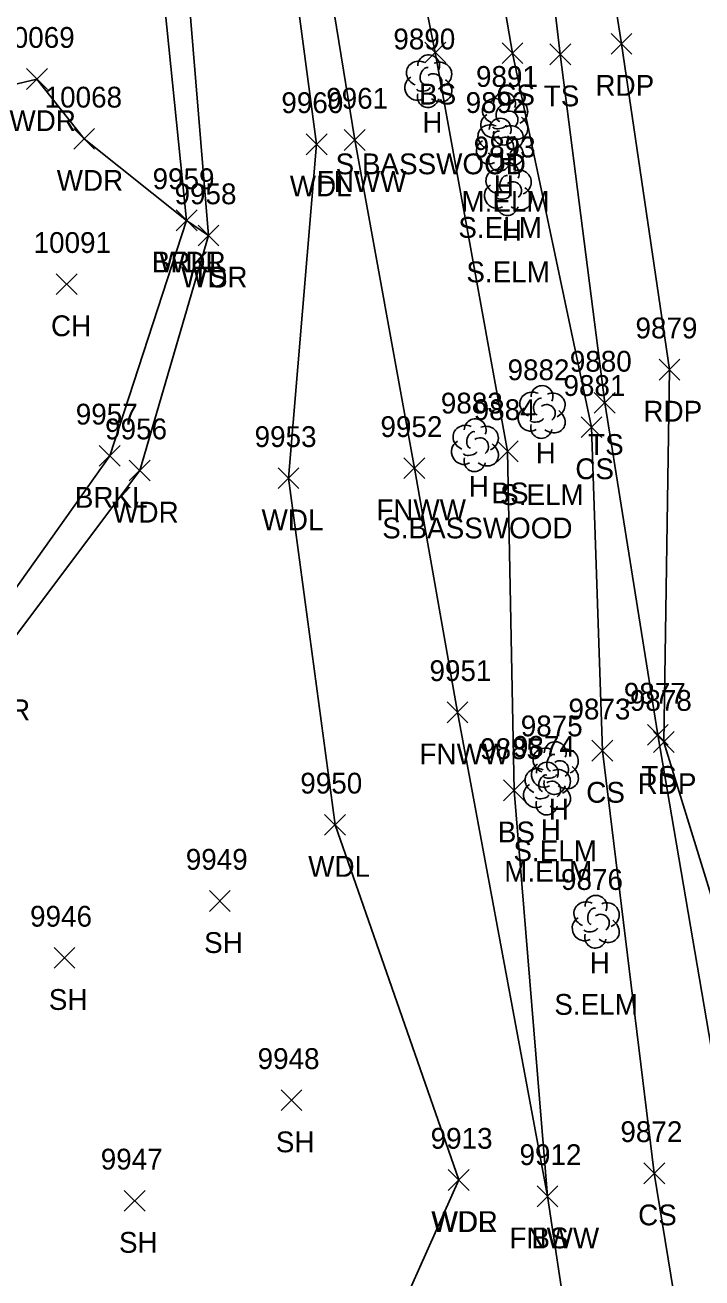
# Model space of a CAD drawing. Extents: x 1439173 to 1457902, y 641926 to 659889.
# Drawn here: x 1448141.5 to 1448206.5, y 646731.6 to 646852 of the extents above; entities that cross this region are included whole.
import ezdxf

# ---------------------------------------------------------------- set-up
doc = ezdxf.new("R2010")
doc.units = 0
for name, color, linetype in [('L_A', 7, 'Continuous'), ('L_C', 7, 'Continuous'), ('L_I', 7, 'Continuous'), ('L_TIC', 7, 'Continuous'), ('LAWA', 7, 'Continuous'), ('LAWE', 7, 'Continuous'), ('LELB', 7, 'Continuous'), ('LFNC', 7, 'Continuous'), ('LTD', 7, 'Continuous'), ('P_A', 7, 'Continuous'), ('P_I', 7, 'Continuous'), ('P_TIC', 7, 'Continuous'), ('PET', 7, 'Continuous')]:
    doc.layers.add(name, color=color, linetype=linetype)

msp = doc.modelspace()

# ---------------------------------------------------------------- linework, layer by layer
at = {"layer": 'L_TIC'}
for points in [[(1448179.87, 646848.4), (1448181.87, 646850.4)], [(1448181.87, 646848.4), (1448179.87, 646850.4)], [(1448187.29, 646848.33), (1448189.29, 646850.33)], [(1448189.29, 646848.33), (1448187.29, 646850.33)], [(1448187.29, 646848.33), (1448189.29, 646850.33)], [(1448189.29, 646848.33), (1448187.29, 646850.33)], [(1448191.88, 646848.23), (1448193.88, 646850.23)], [(1448193.88, 646848.23), (1448191.88, 646850.23)], [(1448141.6, 646845.85), (1448143.6, 646847.85)], [(1448143.6, 646845.85), (1448141.6, 646847.85)], [(1448146.14, 646840.11), (1448148.14, 646842.11)], [(1448148.14, 646840.11), (1448146.14, 646842.11)], [(1448168.47, 646839.58), (1448170.47, 646841.58)], [(1448170.47, 646839.58), (1448168.47, 646841.58)], [(1448172.13, 646840), (1448174.13, 646842)], [(1448174.13, 646840), (1448172.13, 646842)], [(1448155.98, 646832.27), (1448157.98, 646834.27)], [(1448157.98, 646832.27), (1448155.98, 646834.27)], [(1448155.98, 646832.27), (1448157.98, 646834.27)], [(1448157.98, 646832.27), (1448155.98, 646834.27)], [(1448158.08, 646830.82), (1448160.08, 646832.82)], [(1448160.08, 646830.82), (1448158.08, 646832.82)], [(1448158.08, 646830.82), (1448160.08, 646832.82)], [(1448160.08, 646830.82), (1448158.08, 646832.82)], [(1448144.46, 646826.14), (1448146.46, 646828.14)], [(1448146.46, 646826.14), (1448144.46, 646828.14)], [(1448196.14, 646814.73), (1448198.14, 646816.73)], [(1448198.14, 646814.73), (1448196.14, 646816.73)], [(1448194.88, 646812.4), (1448196.88, 646814.4)], [(1448196.88, 646812.4), (1448194.88, 646814.4)], [(1448148.59, 646809.65), (1448150.59, 646811.65)], [(1448150.59, 646809.65), (1448148.59, 646811.65)], [(1448186.82, 646810.08), (1448188.82, 646812.08)], [(1448188.82, 646810.08), (1448186.82, 646812.08)], [(1448186.82, 646810.08), (1448188.82, 646812.08)], [(1448188.82, 646810.08), (1448186.82, 646812.08)], [(1448151.47, 646808.23), (1448153.47, 646810.23)], [(1448153.47, 646808.23), (1448151.47, 646810.23)], [(1448177.86, 646808.45), (1448179.86, 646810.45)], [(1448179.86, 646808.45), (1448177.86, 646810.45)], [(1448165.77, 646807.49), (1448167.77, 646809.49)], [(1448167.77, 646807.49), (1448165.77, 646809.49)], [(1448182.01, 646785), (1448184.01, 646787)], [(1448184.01, 646785), (1448182.01, 646787)], [(1448201.24, 646782.83), (1448203.24, 646784.83)], [(1448203.24, 646782.83), (1448201.24, 646784.83)], [(1448195.92, 646781.31), (1448197.92, 646783.31)], [(1448197.92, 646781.31), (1448195.92, 646783.31)], [(1448187.43, 646777.5), (1448189.43, 646779.5)], [(1448189.43, 646777.5), (1448187.43, 646779.5)], [(1448170.24, 646774.19), (1448172.24, 646776.19)], [(1448172.24, 646774.19), (1448170.24, 646776.19)], [(1448159.17, 646766.87), (1448161.17, 646768.87)], [(1448161.17, 646766.87), (1448159.17, 646768.87)], [(1448144.25, 646761.4), (1448146.25, 646763.4)], [(1448146.25, 646761.4), (1448144.25, 646763.4)], [(1448166.06, 646747.72), (1448168.06, 646749.72)], [(1448168.06, 646747.72), (1448166.06, 646749.72)], [(1448200.91, 646740.7), (1448202.91, 646742.7)], [(1448202.91, 646740.7), (1448200.91, 646742.7)], [(1448182.12, 646740.06), (1448184.12, 646742.06)], [(1448184.12, 646740.06), (1448182.12, 646742.06)], [(1448182.12, 646740.06), (1448184.12, 646742.06)], [(1448184.12, 646740.06), (1448182.12, 646742.06)], [(1448150.99, 646738.06), (1448152.99, 646740.06)], [(1448152.99, 646738.06), (1448150.99, 646740.06)], [(1448190.65, 646738.49), (1448192.65, 646740.49)], [(1448192.65, 646738.49), (1448190.65, 646740.49)], [(1448190.65, 646738.49), (1448192.65, 646740.49)], [(1448192.65, 646738.49), (1448190.65, 646740.49)]]:
    msp.add_lwpolyline(points, dxfattribs=at)
at = {"layer": 'LAWA'}
for points in [[(1448183.12, 646741.06), (1448171.24, 646775.19), (1448166.77, 646808.49), (1448169.47, 646840.58), (1448166.51, 646862.79), (1448166.95, 646881.82), (1448167.02, 646894.53), (1448164.97, 646897.76), (1448155.95, 646904.34), (1448145.42, 646911.6), (1448139.79, 646908.56)], [(1448122.26, 646730.64), (1448122.34, 646733.36), (1448124.58, 646744.9), (1448118.56, 646753.05), (1448120.3, 646764.71), (1448138.2, 646790.24), (1448152.47, 646809.23), (1448159.08, 646831.82), (1448156.98, 646833.27), (1448147.14, 646841.11), (1448142.6, 646846.85), (1448137.7, 646845.7), (1448133.51, 646846.6), (1448126.04, 646850.08), (1448117.8, 646850.56), (1448101.43, 646849.6), (1448092.75, 646843.14), (1448093.37, 646850.31), (1448088.78, 646863.36)], [(1448183.12, 646741.06), (1448174.83, 646722.49)]]:
    msp.add_lwpolyline(points, dxfattribs=at)
at = {"layer": 'LAWE'}
msp.add_lwpolyline([(1448119.67, 646730.17), (1448121.01, 646743.71), (1448116.17, 646751.8), (1448115.93, 646763.95), (1448135.32, 646790.55), (1448149.59, 646810.65), (1448156.98, 646833.27), (1448154.13, 646861.31)], dxfattribs=at)
at = {"layer": 'LELB'}
for points in [[(1448221.02, 646679.97), (1448216.65, 646707.27), (1448209.17, 646743.3), (1448202.24, 646783.83), (1448197.14, 646815.73), (1448192.88, 646849.23), (1448188.79, 646883.91), (1448185.57, 646916.7), (1448180.61, 646928.95), (1448176.05, 646935.8), (1448168.91, 646942.17), (1448163.03, 646939.76)], [(1448188.29, 646849.33), (1448182.45, 646883.23), (1448180.07, 646902.07), (1448180.06, 646909.38)], [(1448159.08, 646831.82), (1448156.64, 646861.39), (1448153.18, 646884.54), (1448157.08, 646891.59), (1448167.02, 646894.53), (1448174.4, 646898.52), (1448175.16, 646902.85)], [(1448187.82, 646811.08), (1448180.87, 646849.4), (1448174.09, 646883.06), (1448180.07, 646902.07)], [(1448185.32, 646643.7), (1448191.92, 646652.09), (1448196.88, 646659.22), (1448211.78, 646670.71), (1448213.3, 646681.39), (1448207.76, 646705.84), (1448201.91, 646741.7), (1448196.92, 646782.31), (1448195.88, 646813.4), (1448188.29, 646849.33)], [(1448187.82, 646811.08), (1448188.43, 646778.5), (1448191.65, 646739.49)]]:
    msp.add_lwpolyline(points, dxfattribs=at)
at = {"layer": 'LFNC'}
msp.add_lwpolyline([(1448099.82, 646655.95), (1448102.02, 646656.12), (1448112.07, 646658.89), (1448125.11, 646661.46), (1448146.72, 646665.17), (1448181.19, 646670.55), (1448193.45, 646673.01), (1448200.73, 646682.46), (1448197.31, 646702.04), (1448191.65, 646739.49), (1448183.01, 646786), (1448178.86, 646809.45), (1448173.13, 646841), (1448169.61, 646862.71), (1448166.95, 646881.82), (1448157.08, 646891.59), (1448153.58, 646895.82), (1448145.42, 646911.6)], dxfattribs=at)
at = {"layer": 'LTD'}
for p, q in [((1448180.18, 646846.7), (1448180.18, 646846.7)), ((1448180.18, 646846.7), (1448180.18, 646846.7)), ((1448187.48, 646843.1), (1448187.48, 646843.1)), ((1448187.48, 646843.1), (1448187.48, 646843.1)), ((1448187.05, 646840.59), (1448187.05, 646840.59)), ((1448187.05, 646840.59), (1448187.05, 646840.59)), ((1448187.82, 646836.32), (1448187.82, 646836.32)), ((1448187.82, 646836.32), (1448187.82, 646836.32)), ((1448191.07, 646814.91), (1448191.07, 646814.91)), ((1448191.07, 646814.91), (1448191.07, 646814.91)), ((1448184.66, 646811.71), (1448184.66, 646811.71)), ((1448184.66, 646811.71), (1448184.66, 646811.71)), ((1448192.34, 646780.69), (1448192.34, 646780.69)), ((1448192.34, 646780.69), (1448192.34, 646780.69)), ((1448191.58, 646778.72), (1448191.58, 646778.72)), ((1448191.58, 646778.72), (1448191.58, 646778.72)), ((1448196.26, 646765.93), (1448196.26, 646765.93)), ((1448196.26, 646765.93), (1448196.26, 646765.93))]:
    msp.add_line(p, q, dxfattribs=at)
for centre in [(1448180.23, 646848.13), (1448187.52, 646844.54), (1448187.1, 646842.03), (1448187.87, 646837.76), (1448191.12, 646816.34), (1448184.7, 646813.15), (1448192.39, 646782.12), (1448191.63, 646780.16), (1448196.31, 646767.36)]:
    msp.add_arc(centre, 1.05, 335.5272, 180.9563, dxfattribs=at)
for centre, major_axis, ratio, start_param, end_param in [((1448179.39, 646847.37), (1.21, -0.51), 0.895232, 1.570796, 4.712389), ((1448181.22, 646847.28), (-1.14, -0.48), 0.949671, 1.570796, 4.712389), ((1448179.97, 646847.16), (-0.208, -0.792), 0.645439, 3.141593, 6.283185), ((1448180.68, 646846.53), (-0.5, 0.667), 0.989748, 3.141593, 6.283185), ((1448179.1, 646845.99), (0.58, -1.04), 0.959034, 3.141593, 6.283185), ((1448179.72, 646845.95), (-0.625, -0.083), 0.423636, 0, 3.141593), ((1448181.18, 646845.87), (-1.09, 0.79), 0.841452, 1.570796, 4.712389), ((1448180.18, 646845.2), (0.26, 1.06), 0.942809, 1.570796, 4.712389), ((1448186.68, 646843.77), (1.21, -0.51), 0.895232, 1.570796, 4.712389), ((1448188.52, 646843.69), (-1.14, -0.48), 0.949671, 1.570796, 4.712389), ((1448187.27, 646843.56), (-0.208, -0.792), 0.645439, 3.141593, 6.283185), ((1448187.98, 646842.94), (-0.5, 0.667), 0.989748, 3.141593, 6.283185), ((1448186.26, 646841.26), (1.21, -0.51), 0.895232, 1.570796, 4.712389), ((1448186.39, 646842.39), (0.58, -1.04), 0.959034, 3.141593, 6.283185), ((1448187.02, 646842.35), (-0.625, -0.083), 0.423636, 0, 3.141593), ((1448188.09, 646841.18), (-1.14, -0.48), 0.949671, 1.570796, 4.712389), ((1448188.48, 646842.27), (-1.09, 0.79), 0.841452, 1.570796, 4.712389), ((1448186.84, 646841.05), (-0.208, -0.792), 0.645439, 3.141593, 6.283185), ((1448187.48, 646841.6), (0.26, 1.06), 0.942809, 1.570796, 4.712389), ((1448187.55, 646840.43), (-0.5, 0.667), 0.989748, 3.141593, 6.283185), ((1448185.97, 646839.88), (0.58, -1.04), 0.959034, 3.141593, 6.283185), ((1448186.59, 646839.84), (-0.625, -0.083), 0.423636, 0, 3.141593), ((1448188.05, 646839.76), (-1.09, 0.79), 0.841452, 1.570796, 4.712389), ((1448187.05, 646839.09), (0.26, 1.06), 0.942809, 1.570796, 4.712389), ((1448187.03, 646836.99), (1.21, -0.51), 0.895232, 1.570796, 4.712389), ((1448187.61, 646836.78), (-0.208, -0.792), 0.645439, 3.141593, 6.283185), ((1448188.86, 646836.91), (-1.14, -0.48), 0.949671, 1.570796, 4.712389), ((1448186.74, 646835.61), (0.58, -1.04), 0.959034, 3.141593, 6.283185), ((1448188.32, 646836.16), (-0.5, 0.667), 0.989748, 3.141593, 6.283185), ((1448188.82, 646835.49), (-1.09, 0.79), 0.841452, 1.570796, 4.712389), ((1448187.82, 646834.82), (0.26, 1.06), 0.942809, 1.570796, 4.712389), ((1448187.36, 646835.57), (-0.625, -0.083), 0.423636, 0, 3.141593), ((1448190.28, 646815.57), (1.21, -0.51), 0.895232, 1.570796, 4.712389), ((1448190.86, 646815.37), (-0.208, -0.792), 0.645439, 3.141593, 6.283185), ((1448192.11, 646815.49), (-1.14, -0.48), 0.949671, 1.570796, 4.712389), ((1448189.99, 646814.2), (0.58, -1.04), 0.959034, 3.141593, 6.283185), ((1448191.57, 646814.74), (-0.5, 0.667), 0.989748, 3.141593, 6.283185), ((1448192.07, 646814.07), (-1.09, 0.79), 0.841452, 1.570796, 4.712389), ((1448183.87, 646812.38), (1.21, -0.51), 0.895232, 1.570796, 4.712389), ((1448185.7, 646812.3), (-1.14, -0.48), 0.949671, 1.570796, 4.712389), ((1448191.07, 646813.41), (0.26, 1.06), 0.942809, 1.570796, 4.712389), ((1448190.61, 646814.16), (-0.625, -0.083), 0.423636, 0, 3.141593), ((1448184.45, 646812.17), (-0.208, -0.792), 0.645439, 3.141593, 6.283185), ((1448185.16, 646811.55), (-0.5, 0.667), 0.989748, 3.141593, 6.283185), ((1448183.57, 646811), (0.58, -1.04), 0.959034, 3.141593, 6.283185), ((1448184.2, 646810.96), (-0.625, -0.083), 0.423636, 0, 3.141593), ((1448185.66, 646810.88), (-1.09, 0.79), 0.841452, 1.570796, 4.712389), ((1448184.66, 646810.21), (0.26, 1.06), 0.942809, 1.570796, 4.712389), ((1448191.55, 646781.36), (1.21, -0.51), 0.895232, 1.570796, 4.712389), ((1448193.38, 646781.27), (-1.14, -0.48), 0.949671, 1.570796, 4.712389), ((1448191.26, 646779.98), (0.58, -1.04), 0.959034, 3.141593, 6.283185), ((1448192.13, 646781.15), (-0.208, -0.792), 0.645439, 3.141593, 6.283185), ((1448192.84, 646780.52), (-0.5, 0.667), 0.989748, 3.141593, 6.283185), ((1448190.79, 646779.39), (1.21, -0.51), 0.895232, 1.570796, 4.712389), ((1448191.37, 646779.18), (-0.208, -0.792), 0.645439, 3.141593, 6.283185), ((1448191.89, 646779.94), (-0.625, -0.083), 0.423636, 0, 3.141593), ((1448192.62, 646779.31), (-1.14, -0.48), 0.949671, 1.570796, 4.712389), ((1448193.34, 646779.86), (-1.09, 0.79), 0.841452, 1.570796, 4.712389), ((1448190.5, 646778.01), (0.58, -1.04), 0.959034, 3.141593, 6.283185), ((1448192.34, 646779.19), (0.26, 1.06), 0.942809, 1.570796, 4.712389), ((1448192.08, 646778.55), (-0.5, 0.667), 0.989748, 3.141593, 6.283185), ((1448192.58, 646777.89), (-1.09, 0.79), 0.841452, 1.570796, 4.712389), ((1448191.58, 646777.22), (0.26, 1.06), 0.942809, 1.570796, 4.712389), ((1448191.12, 646777.97), (-0.625, -0.083), 0.423636, 0, 3.141593), ((1448195.47, 646766.59), (1.21, -0.51), 0.895232, 1.570796, 4.712389), ((1448197.31, 646766.51), (-1.14, -0.48), 0.949671, 1.570796, 4.712389), ((1448196.06, 646766.39), (-0.208, -0.792), 0.645439, 3.141593, 6.283185), ((1448196.76, 646765.76), (-0.5, 0.667), 0.989748, 3.141593, 6.283185), ((1448195.18, 646765.22), (0.58, -1.04), 0.959034, 3.141593, 6.283185), ((1448195.81, 646765.18), (-0.625, -0.083), 0.423636, 0, 3.141593), ((1448197.26, 646765.1), (-1.09, 0.79), 0.841452, 1.570796, 4.712389), ((1448196.26, 646764.43), (0.26, 1.06), 0.942809, 1.570796, 4.712389)]:
    msp.add_ellipse(centre, major_axis=major_axis, ratio=ratio, start_param=start_param, end_param=end_param, dxfattribs=at)
at = {"layer": 'P_TIC'}
for points in [[(1448197.76, 646849.24), (1448199.76, 646851.24)], [(1448199.76, 646849.24), (1448197.76, 646851.24)], [(1448202.37, 646817.93), (1448204.37, 646819.93)], [(1448204.37, 646817.93), (1448202.37, 646819.93)], [(1448201.82, 646782.14), (1448203.82, 646784.14)], [(1448203.82, 646782.14), (1448201.82, 646784.14)]]:
    msp.add_lwpolyline(points, dxfattribs=at)
at = {"layer": 'PET'}
msp.add_lwpolyline([(1448246.46, 646550.34), (1448240.19, 646586.21), (1448237.44, 646603.85), (1448232.82, 646631.59), (1448226.85, 646667.5), (1448220.22, 646707.78), (1448215.23, 646742.97), (1448202.82, 646783.14), (1448203.37, 646818.93), (1448198.76, 646850.24), (1448193.44, 646884.14), (1448187.94, 646917.18), (1448185.3, 646933.85), (1448181.56, 646957.89), (1448177.35, 646983.4)], dxfattribs=at)

# ---------------------------------------------------------------- texts
at = {"layer": 'L_A'}
for s, p in [('BS', (1448179.31, 646844.4)), ('CS', (1448186.73, 646844.33)), ('CS', (1448186.73, 646844.33)), ('TS', (1448191.29, 646844.23)), ('WDR', (1448139.96, 646841.85)), ('H', (1448179.62, 646841.7)), ('H', (1448186.91, 646838.1)), ('WDR', (1448144.5, 646836.11)), ('WDL', (1448166.89, 646835.58)), ('FNWW', (1448169.48, 646836)), ('H', (1448186.49, 646835.59)), ('H', (1448187.25, 646831.32)), ('BRKL', (1448153.63, 646828.27)), ('WDR', (1448154.34, 646828.27)), ('WDR', (1448156.44, 646826.82)), ('TS', (1448157.49, 646826.82)), ('CH', (1448143.95, 646822.14)), ('TS', (1448195.55, 646810.73)), ('H', (1448190.51, 646809.91)), ('CS', (1448194.32, 646808.4)), ('H', (1448184.09, 646806.71)), ('BRKL', (1448146.24, 646805.65)), ('BS', (1448186.26, 646806.08)), ('BS', (1448186.26, 646806.08)), ('WDR', (1448149.83, 646804.23)), ('FNWW', (1448175.2, 646804.45)), ('WDL', (1448164.18, 646803.49)), ('WDR', (1448135.56, 646785.24)), ('FNWW', (1448179.35, 646781)), ('TS', (1448200.65, 646778.83)), ('CS', (1448195.37, 646777.31)), ('H', (1448191.78, 646775.69)), ('BS', (1448186.87, 646773.5)), ('H', (1448191.01, 646773.72)), ('WDL', (1448168.66, 646770.19)), ('SH', (1448158.66, 646762.87)), ('H', (1448195.7, 646760.93)), ('SH', (1448143.74, 646757.4)), ('SH', (1448165.55, 646743.72)), ('CS', (1448200.35, 646736.7)), ('WDR', (1448180.48, 646736.06)), ('WDL', (1448180.53, 646736.06)), ('FNWW', (1448188, 646734.49)), ('BS', (1448190.1, 646734.49)), ('SH', (1448150.48, 646734.06))]:
    msp.add_text(s, height=2, dxfattribs=at).set_placement(p)
at = {"layer": 'L_C'}
for s, p in [('S.BASSWOOD', (1448171.29, 646837.7)), ('M.ELM', (1448183.38, 646834.1)), ('S.ELM', (1448183.08, 646831.59)), ('S.ELM', (1448183.85, 646827.32)), ('S.ELM', (1448187.1, 646805.91)), ('S.BASSWOOD', (1448175.77, 646802.71)), ('S.ELM', (1448188.37, 646771.69)), ('M.ELM', (1448187.49, 646769.72)), ('S.ELM', (1448192.3, 646756.93))]:
    msp.add_text(s, height=2, dxfattribs=at).set_placement(p)
at = {"layer": 'L_I'}
for s, p in [('10069', (1448138.79, 646849.85)), ('9890', (1448176.84, 646849.7)), ('9891', (1448184.78, 646846.1)), ('10068', (1448143.34, 646844.11)), ('9961', (1448170.39, 646844)), ('9960', (1448166.08, 646843.58)), ('9892', (1448183.79, 646843.59)), ('9893', (1448184.56, 646839.32)), ('9959', (1448153.71, 646836.27)), ('9959', (1448153.71, 646836.27)), ('9958', (1448155.82, 646834.82)), ('9958', (1448155.82, 646834.82)), ('10091', (1448142.28, 646830.14)), ('9880', (1448193.79, 646818.73)), ('9882', (1448187.81, 646817.91)), ('9881', (1448193.18, 646816.4)), ('9883', (1448181.4, 646814.71)), ('9884', (1448184.56, 646814.08)), ('9884', (1448184.56, 646814.08)), ('9957', (1448146.33, 646813.65)), ('9956', (1448149.15, 646812.23)), ('9953', (1448163.51, 646811.49)), ('9952', (1448175.6, 646812.45)), ('9951', (1448180.31, 646789)), ('9877', (1448198.98, 646786.83)), ('9873', (1448193.66, 646785.31)), ('9875', (1448189.08, 646783.69)), ('9885', (1448185.17, 646781.5)), ('9874', (1448188.32, 646781.72)), ('9950', (1448167.9, 646778.19)), ('9949', (1448156.9, 646770.87)), ('9876', (1448192.95, 646768.93)), ('9946', (1448141.94, 646765.4)), ('9948', (1448163.8, 646751.72)), ('9913', (1448180.42, 646744.06)), ('9913', (1448180.42, 646744.06)), ('9872', (1448198.65, 646744.7)), ('9947', (1448148.73, 646742.06)), ('9912', (1448188.96, 646742.49)), ('9912', (1448188.96, 646742.49))]:
    msp.add_text(s, height=2, dxfattribs=at).set_placement(p)
at = {"layer": 'P_A'}
for p in [(1448196.25, 646845.24), (1448200.86, 646813.93), (1448200.31, 646778.14)]:
    msp.add_text('RDP', height=2, dxfattribs=at).set_placement(p)
at = {"layer": 'P_I'}
for s, p in [('9879', (1448200.1, 646821.93)), ('9878', (1448199.56, 646786.14))]:
    msp.add_text(s, height=2, dxfattribs=at).set_placement(p)

doc.saveas('drawing.dxf')
